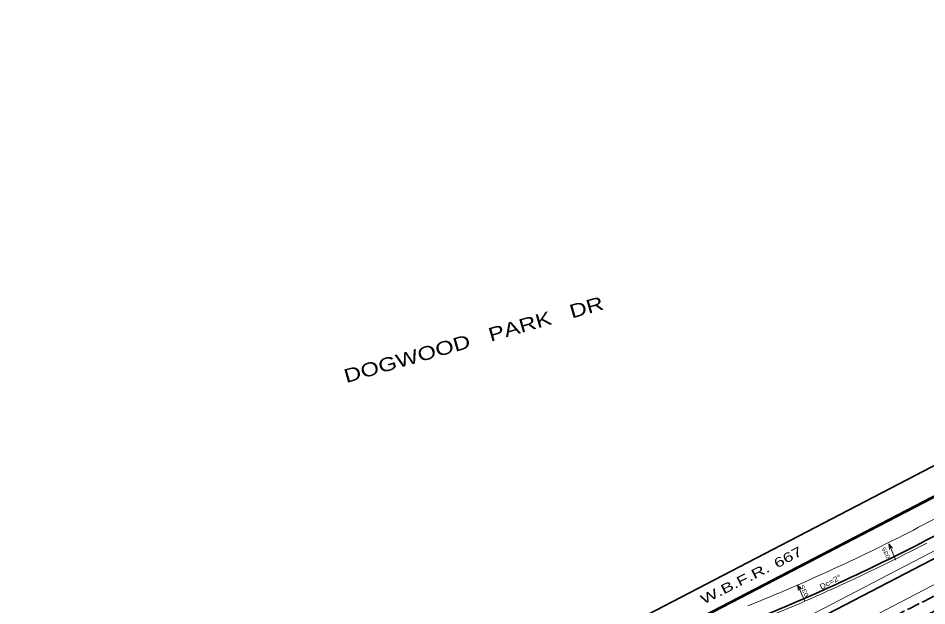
# Model space of a CAD drawing. Extents: x 2354993 to 2372084, y 6966390 to 6990057.
# Drawn here: x 2361674 to 2363006, y 6978319 to 6979180 of the extents above; entities that cross this region are included whole.
import ezdxf
from ezdxf.enums import TextEntityAlignment as Align

# ---------------------------------------------------------------- set-up
doc = ezdxf.new("R2010")
doc.units = 0
doc.header["$LTSCALE"] = 3.2
doc.linetypes.add('LONG_DASHED', pattern=[7.5, 6, -1.5])
for name, color, linetype, lineweight in [('13', 7, 'Continuous', 13), ('17', 7, 'Continuous', 13), ('19', 7, 'Continuous', 13), ('2', 7, 'Continuous', 35), ('4', 7, 'Continuous', 13), ('5', 7, 'Continuous', 35), ('9', 7, 'Continuous', 13)]:
    doc.layers.add(name, color=color, linetype=linetype, lineweight=lineweight)

msp = doc.modelspace()

# ---------------------------------------------------------------- linework, layer by layer
at = {"layer": '19'}
for p, q in [((2362949.899, 6978409.967), (2362951.045, 6978401.741)), ((2362949.899, 6978409.967), (2362955.212, 6978403.576)), ((2362960.316, 6978386.382), (2362949.899, 6978409.967)), ((2362816.435, 6978349.953), (2362817.581, 6978341.727)), ((2362816.435, 6978349.953), (2362821.748, 6978343.562)), ((2362826.852, 6978326.368), (2362816.435, 6978349.953))]:
    msp.add_line(p, q, dxfattribs=at)
at = {"layer": '2'}
for p, q in [((2358006.591, 6975920.846), (2363488.891, 6978770.331)), ((2363003.914, 6978414.83), (2363230.047, 6978532.352))]:
    msp.add_line(p, q, dxfattribs=at)
at = {"layer": '2', "linetype": 'LONG_DASHED'}
msp.add_arc((2361957.93, 6980359.697), 2285.831, 293.48147, 297.64944, dxfattribs=at)
at = {"layer": '4'}
msp.add_line((2362757.154, 6978215.587), (2363268.695, 6978481.438), dxfattribs=at)
at = {"layer": '5'}
for p, q in [((2362087.371, 6978041.876), (2363419.143, 6978734.078)), ((2362654.988, 6978292.473), (2363507.292, 6978735.395)), ((2362655.626, 6978291.114), (2363508.018, 6978734.082)), ((2362391.142, 6978063.692), (2363583.984, 6978683.611))]:
    msp.add_line(p, q, dxfattribs=at)
at = {"layer": '5', "lineweight": 13}
for p, q in [((2362993.757, 6978434.346), (2363229.499, 6978556.861)), ((2362329.78, 6978043.07), (2363248.405, 6978520.479))]:
    msp.add_line(p, q, dxfattribs=at)
for radius, start in [(2856.789, 291.93666), (2882.789, 291.73437)]:
    msp.add_arc((2361676.37, 6980969.25), radius, start, 297.46082, dxfattribs=at)
at = {"layer": '5'}
for centre, radius, start, end in [((2361676.37, 6980969.25), 2878.789, 291.93666, 297.46082), ((2361968.189, 6980365.073), 2305.831, 293.48164, 297.64942)]:
    msp.add_arc(centre, radius, start, end, dxfattribs=at)
at = {"layer": '9'}
msp.add_arc((2360722.521, 6984327.136), 5729.573, 359.50797, 359.50797, dxfattribs=at)

# ---------------------------------------------------------------- texts
at = {"layer": '13', "width": 1.3}
msp.add_text('DOGWOOD   PARK   DR', height=20, rotation=15.972, dxfattribs=at).set_placement((2362344.408, 6978699.867), align=Align.CENTER)
at = {"layer": '13'}
for s, rotation, width, p in [('667', 28.354, 1.4, (2362786.363, 6978373.913)), ('W.B.F.R.', 26.495, 1.45, (2362678.535, 6978321.105))]:
    msp.add_text(s, height=14, rotation=rotation, dxfattribs=dict(at, width=width)).set_placement(p)
at = {"layer": '17', "width": 1.15}
msp.add_text('Dc=2°', height=8, rotation=27.643, dxfattribs=at).set_placement((2362851.244, 6978342.856))
at = {"layer": '19', "width": 1.35}
for p in [(2362953.65, 6978387.324), (2362834.169, 6978331.502)]:
    msp.add_text('.035', height=5.999, rotation=115.33, dxfattribs=at).set_placement(p)

doc.saveas('drawing.dxf')
